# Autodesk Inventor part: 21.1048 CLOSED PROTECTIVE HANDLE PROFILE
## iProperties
Created: 2007-02
Part Number: 21.1048 CLOSED PROTECTIVE HANDLE PROFILE
Material: Aluminum-6061
Document SubType Name: Modeling
Designer: Andy Moles
Density: 2.71 g/cm^3
Author: Andy Moles
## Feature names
1. Extrusion1
